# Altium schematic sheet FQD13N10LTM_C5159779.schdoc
size 127 x 101 mm
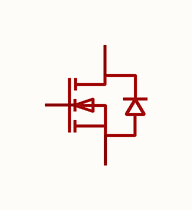
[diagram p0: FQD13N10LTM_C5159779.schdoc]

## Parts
Q?  fqd13n10ltm(umw)  [TO-252-2_L6.6-W6.1-P4.57-LS9.9-BR-CW]  (value not drawn)

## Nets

Not connected (* = marked no-connect by the designer): Q? 1(G) 2(D) 3(S)

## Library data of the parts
Q? = fqd13n10ltm(umw): 数量:1个N沟道;漏源电压(Vdss):100V;连续漏极电流(Id):10A;导通电阻(RDS(on)):142mΩ@10V;耗散功率(Pd):40W;阈值电压(Vgs(th)):2V;; Manufacturer: UMW(友台半导体); Symbol: FQD13N10LTM_C5159779; AddInBom: yes; ModelId: ce57f84d66384067af8a68020b6de06d; ModelName: TO-252-2L-3P_L6.6-W6.1-H2.3-LS10.1-P4.6; ModelTransform: 259.842,390.52442,0,90,0,0,-39.39,0,0; Number: 1个N沟道; Drain to Source Voltage: 100V; Current - Continuous Drain(Id): 10A; Pd - Power Dissipation: 40W; Gate Threshold Voltage (Vgs(th)): 2V; Gate Charge(Qg): 12nC; Input Capacitance(Ciss): 400pF; Reverse Transfer Capacitance (Crss@Vds): 20pF; Output Capacitance(Coss): 95pF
